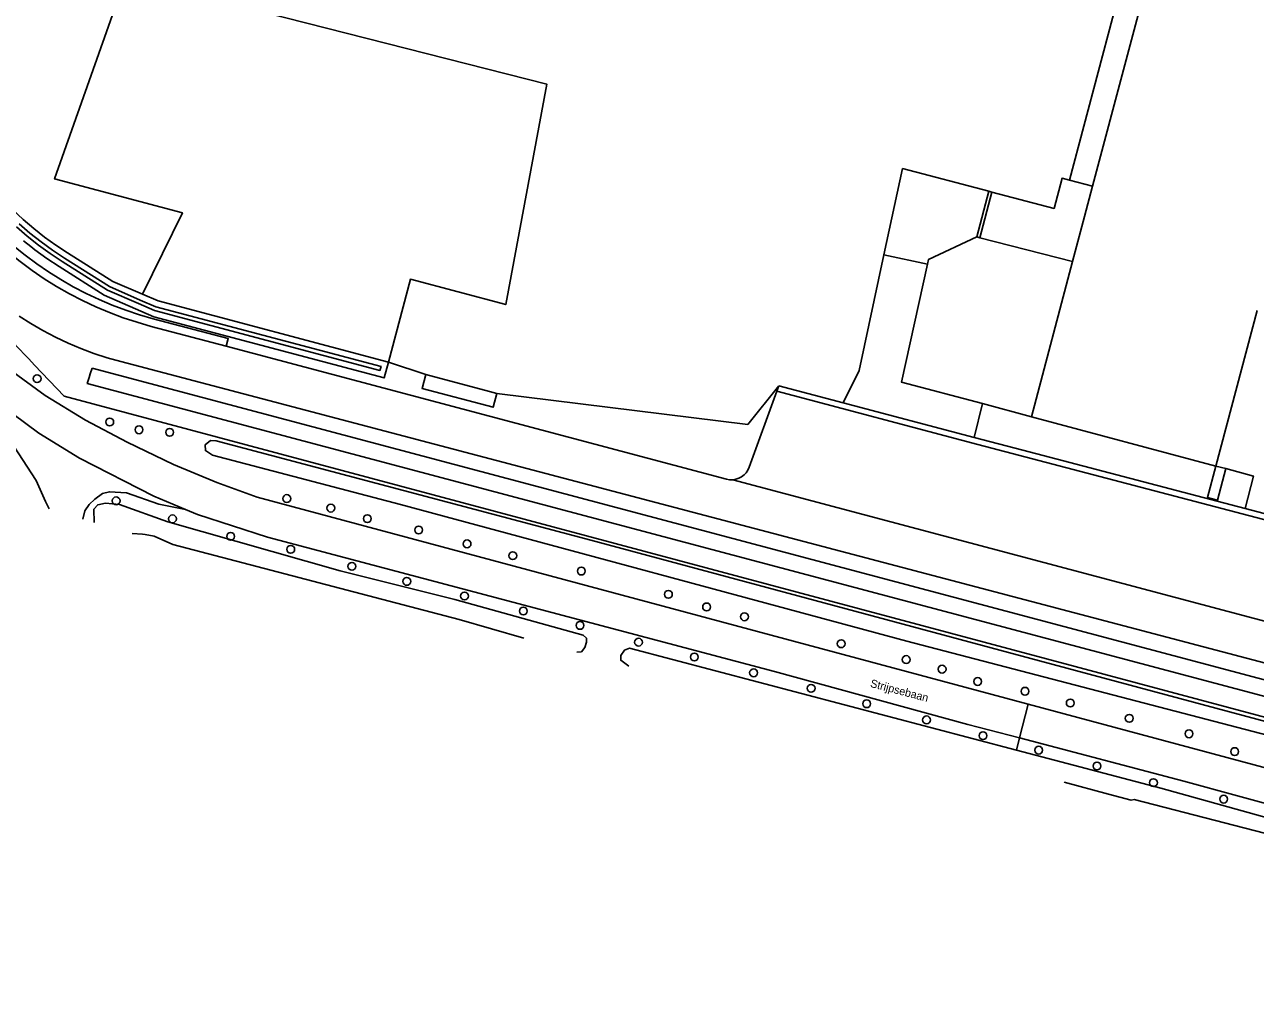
# Model space of a CAD drawing. Extents: x 152881 to 155736, y 382924 to 386919.
# Drawn here: x 154029.1 to 154182.8, y 383105 to 383226.3 of the extents above; entities that cross this region are included whole.
import ezdxf

# ---------------------------------------------------------------- set-up
doc = ezdxf.new("R2010")
doc.units = 0
for name, color, linetype in [('IMGEO_Boom', 7, 'Continuous'), ('IMGEO_Groenvoorziening', 7, 'Continuous'), ('IMGEO_Hek', 7, 'Continuous'), ('IMGEO_Loofbos', 7, 'Continuous'), ('IMGEO_Openbare_ruimte_label', 7, 'Continuous'), ('IMGEO_Pand', 7, 'Continuous'), ('IMGEO_Rijbaan_lokaal_gesloten', 7, 'Continuous'), ('IMGEO_Rijbaan_lokaal_halfverhard', 7, 'Continuous'), ('IMGEO_Rijbaan_lokaal_open', 7, 'Continuous'), ('IMGEO_Voetpad_gesloten', 7, 'Continuous'), ('IMGEO_Voetpad_op_trap', 7, 'Continuous'), ('IMGEO_Voetpad_open', 7, 'Continuous'), ('IMGEO_Waterloop', 7, 'Continuous')]:
    doc.layers.add(name, color=color, linetype=linetype)

msp = doc.modelspace()

# ---------------------------------------------------------------- linework, layer by layer
at = {"layer": 'IMGEO_Boom'}
for centre in [(154030.64, 383182.09), (154039.71, 383176.67), (154043.37, 383175.7), (154047.19, 383175.38), (154040.51, 383166.82), (154061.83, 383167.1), (154067.33, 383165.91), (154047.55, 383164.57), (154071.89, 383164.59), (154054.82, 383162.38), (154078.3, 383163.18), (154062.32, 383160.76), (154084.35, 383161.44), (154090.06, 383159.96), (154069.96, 383158.63), (154098.63, 383158.04), (154076.82, 383156.75), (154084.03, 383154.92), (154109.5, 383155.14), (154091.38, 383153.05), (154114.27, 383153.56), (154098.46, 383151.25), (154119, 383152.33), (154105.77, 383149.15), (154131.09, 383148.96), (154112.74, 383147.3), (154139.21, 383146.98), (154120.14, 383145.33), (154143.69, 383145.78), (154148.13, 383144.24), (154127.33, 383143.39), (154154.05, 383143.02), (154134.27, 383141.46), (154159.7, 383141.55), (154141.75, 383139.44), (154167.07, 383139.64), (154148.8, 383137.47), (154174.54, 383137.71), (154155.76, 383135.66), (154180.24, 383135.48), (154163.04, 383133.68), (154170.09, 383131.59), (154178.87, 383129.54)]:
    msp.add_circle(centre, 0.489, dxfattribs=at)
at = {"layer": 'IMGEO_Groenvoorziening'}
for points in [[(154296.01, 383110.08), (154286.6, 383112.34), (154034.03, 383179.91), (154030.33, 383183.78), (154029.6, 383184.55), (154029.12, 383185.06), (154028.39, 383185.82), (153891.83, 383329), (153882.74, 383329.15), (153882.71, 383329.32)], [(154054.27, 383186.13), (154054.52, 383187.09), (154045.15, 383189.58), (154043.42, 383190.08), (154041.71, 383190.65), (154040.03, 383191.28), (154038.38, 383191.98), (154036.75, 383192.74), (154035.16, 383193.57), (154033.6, 383194.46), (154032.07, 383195.42), (154030.59, 383196.43), (154029.15, 383197.5), (154027.75, 383198.63), (154026.4, 383199.82), (154025.18, 383200.97), (154024.49, 383200.24)], [(154028.94, 383199.31), (154029.85, 383198.59), (154030.37, 383198.18), (154031.86, 383197.11), (154033.38, 383196.1), (154039.02, 383192.53), (154045.21, 383189.83), (154073.99, 383182.18), (154074.52, 383184.16)], [(154074.52, 383184.16), (154045.74, 383191.81), (154043.82, 383192.63)], [(154153.38, 383137.18), (154152.98, 383135.66)]]:
    msp.add_lwpolyline(points, dxfattribs=at)
at = {"layer": 'IMGEO_Hek'}
for points in [[(154028.39, 383185.82), (154029.12, 383185.06)], [(154029.12, 383185.06), (154029.6, 383184.55)], [(154029.6, 383184.55), (154030.33, 383183.78)], [(154294.11, 383119.44), (154295.32, 383113.47), (154296.01, 383110.08), (154286.6, 383112.34), (154034.03, 383179.91), (154030.33, 383183.78)]]:
    msp.add_lwpolyline(points, dxfattribs=at)
at = {"layer": 'IMGEO_Loofbos'}
for points in [[(154165.79, 383480.92), (154156.98, 383466.93), (154155.57, 383464.69), (154156.76, 383463.94), (154167.27, 383457.31), (154127.08, 383391.98), (154141.95, 383313.16), (154155.29, 383289.09), (154162.41, 383252.83), (154169.8, 383245.38), (154168.55, 383240.68), (154159.6, 383206.89)], [(154043.82, 383192.63), (154040.1, 383194.22), (154034.45, 383197.79), (154032.99, 383198.75), (154031.58, 383199.78), (154030.21, 383200.86), (154028.88, 383201.99), (154027.6, 383203.18), (154026.37, 383204.42), (153969.96, 383263.71), (153968.87, 383264.87)], [(154074.52, 383184.16), (154077.27, 383194.5), (154089.18, 383191.34), (154094.3, 383218.9), (154041.72, 383232.3), (154032.81, 383207.04), (154048.79, 383202.79), (154043.82, 383192.63)], [(154079.18, 383182.61), (154074.52, 383184.16)], [(154123.29, 383181.18), (154119.41, 383176.34), (154088.07, 383180.25)]]:
    msp.add_lwpolyline(points, dxfattribs=at)
at = {"layer": 'IMGEO_Pand'}
for points in [[(154173.24, 383237.11), (154170.88, 383237.75), (154162.5, 383206.13)], [(154162.5, 383206.13), (154161.5, 383202.36), (154160, 383196.72)], [(154160, 383196.72), (154154.86, 383177.31)], [(154177.9, 383171.14), (154183.06, 383190.59)], [(154154.86, 383177.31), (154177.9, 383171.14)]]:
    msp.add_lwpolyline(points, dxfattribs=at)
at = {"layer": 'IMGEO_Rijbaan_lokaal_gesloten'}
for points in [[(154054.27, 383186.13), (154044.89, 383188.62), (154043.12, 383189.13), (154041.38, 383189.7), (154039.66, 383190.35), (154037.97, 383191.06), (154036.31, 383191.85), (154034.68, 383192.69), (154033.08, 383193.6), (154031.53, 383194.58), (154030.01, 383195.62), (154028.54, 383196.71), (154027.11, 383197.87), (154025.73, 383199.08), (154024.49, 383200.24)], [(154028.39, 383189.91), (154029.86, 383188.98), (154031.37, 383188.1), (154032.92, 383187.29), (154034.5, 383186.54), (154036.11, 383185.86), (154037.74, 383185.24), (154039.4, 383184.69), (154041.08, 383184.21), (154285.51, 383119.78), (154286.82, 383119.55), (154288.58, 383119.39), (154289.45, 383119.52), (154294.6, 383120.39), (154294.84, 383119.58)], [(154117.53, 383169.45), (154117.14, 383169.46), (154116.76, 383169.53), (154054.27, 383186.13)], [(154123.05, 383180.52), (154119.6, 383171.01), (154119.44, 383170.66), (154119.22, 383170.33), (154118.95, 383170.05), (154118.64, 383169.82), (154118.29, 383169.63), (154117.92, 383169.51), (154117.53, 383169.45)], [(154243.08, 383148.93), (154148.16, 383173.85), (154123.05, 383180.52)], [(154241.31, 383136.53), (154117.53, 383169.45)]]:
    msp.add_lwpolyline(points, dxfattribs=at)
at = {"layer": 'IMGEO_Rijbaan_lokaal_halfverhard'}
for points in [[(154032.13, 383165.8), (154031.68, 383166.72), (154030.54, 383169.34), (154025.99, 383176.29), (154023.57, 383179.52), (154015.93, 383186.56), (154015.99, 383187.44)], [(154049.17, 383165.75), (154045.2, 383167.4), (154035.94, 383172.13), (154030.85, 383175.27), (154024.47, 383179.99), (154015.99, 383187.44)], [(154027.14, 383183.27), (154031.63, 383179.99), (154036.69, 383176.91), (154041.89, 383174.16), (154047.67, 383171.36), (154053.09, 383169.1), (154058.11, 383167.26), (154154.46, 383141.41)], [(154036.35, 383164.54), (154036.61, 383165.57), (154037.13, 383166.34), (154037.85, 383167.04), (154038.82, 383167.72), (154039.68, 383167.95), (154041.81, 383167.83), (154045.84, 383166.42), (154049.17, 383165.75)], [(154153.38, 383137.18), (154146.89, 383138.88), (154122.76, 383145.5), (154059.4, 383162.27), (154050.69, 383165.13), (154049.17, 383165.75)], [(154154.46, 383141.41), (154153.38, 383137.18)], [(154154.46, 383141.41), (154226.11, 383122.18), (154266.39, 383111.73), (154274.12, 383109.53)], [(154272.97, 383105.01), (154250.05, 383111.69), (154234.23, 383115.28), (154173.87, 383131.78), (154153.38, 383137.18)]]:
    msp.add_lwpolyline(points, dxfattribs=at)
at = {"layer": 'IMGEO_Rijbaan_lokaal_open'}
for points in [[(154149.51, 383205.51), (154148.01, 383199.8)], [(154149.9, 383205.41), (154149.51, 383205.51)], [(154148.4, 383199.7), (154149.9, 383205.41)], [(154148.01, 383199.8), (154148.4, 383199.7)], [(154123.29, 383181.18), (154123.05, 383180.52)], [(154131.35, 383179.05), (154123.29, 383181.18)], [(154131.35, 383179.05), (154147.7, 383174.75)], [(154147.7, 383174.75), (154153.76, 383173.16), (154178.04, 383166.77)], [(154178.04, 383166.77), (154181.54, 383165.85)], [(154181.54, 383165.85), (154207.14, 383159.11)]]:
    msp.add_lwpolyline(points, dxfattribs=at)
at = {"layer": 'IMGEO_Voetpad_gesloten'}
for points in [[(154149.51, 383205.51), (154138.75, 383208.34), (154136.43, 383197.55)], [(154159.6, 383206.89), (154158.68, 383207.14), (154157.69, 383203.36), (154149.9, 383205.41)], [(154162.5, 383206.13), (154159.6, 383206.89)], [(154141.86, 383196.39), (154141.99, 383196.97), (154148.01, 383199.8)], [(154160, 383196.72), (154148.4, 383199.7)], [(154141.86, 383196.39), (154136.43, 383197.55)], [(154147.7, 383174.75), (154148.72, 383179)], [(154148.72, 383179), (154154.86, 383177.31)], [(154177.9, 383171.14), (154176.86, 383167.25), (154178.08, 383166.91)], [(154178.08, 383166.91), (154178.04, 383166.77)]]:
    msp.add_lwpolyline(points, dxfattribs=at)
at = {"layer": 'IMGEO_Voetpad_op_trap'}
msp.add_lwpolyline([(154179.13, 383170.84), (154177.9, 383171.14)], dxfattribs=at)
at = {"layer": 'IMGEO_Voetpad_open'}
for points in [[(154136.43, 383197.55), (154133.32, 383183.1), (154131.35, 383179.05)], [(154148.72, 383179), (154138.61, 383181.66), (154141.86, 383196.39)], [(154178.08, 383166.91), (154179.13, 383170.84)], [(154179.13, 383170.84), (154182.6, 383169.88), (154181.54, 383165.85)]]:
    msp.add_lwpolyline(points, dxfattribs=at)
at = {"layer": 'IMGEO_Waterloop'}
for points in [[(154028.38, 383201.43), (154029.73, 383200.28), (154031.13, 383199.18), (154032.57, 383198.14), (154034.04, 383197.16), (154039.68, 383193.59), (154043.52, 383191.91), (154045.48, 383191.07), (154073.6, 383183.61), (154073.47, 383183.12), (154045.32, 383190.6), (154043.32, 383191.46), (154039.44, 383193.15), (154033.77, 383196.74), (154032.28, 383197.73), (154030.83, 383198.78), (154029.41, 383199.89), (154028.05, 383201.06)], [(154037.5, 383183.41), (154037.28, 383182.69), (154037.13, 383182.22), (154036.91, 383181.5), (154279.63, 383116.96), (154285.99, 383114.17), (154286.79, 383116), (154280.29, 383118.85), (154037.5, 383183.41)], [(154079.18, 383182.61), (154078.72, 383180.87), (154087.61, 383178.51), (154088.07, 383180.25)], [(154088.07, 383180.25), (154087.16, 383180.49), (154079.18, 383182.61)], [(154155.86, 383146.84), (154205.05, 383133.61), (154253.56, 383120.41), (154293.05, 383110), (154292.87, 383108.88), (154253.14, 383118.76), (154206.65, 383131.7), (154155.4, 383145.06), (154139.27, 383149.26), (154076.04, 383166.38), (154052.55, 383172.51), (154051.66, 383173.09), (154051.64, 383173.82), (154052.29, 383174.34), (154052.99, 383174.33), (154099.83, 383161.9), (154155.86, 383146.84)], [(154098.08, 383147.9), (154098.63, 383147.93), (154099.05, 383148.48), (154099.28, 383149.14), (154099.25, 383149.67), (154098.86, 383150.01), (154082.83, 383154.48), (154068.49, 383158.08), (154046.97, 383164.18), (154040.91, 383166.35), (154039.17, 383166.52), (154038.22, 383166.32), (154037.74, 383165.79), (154037.76, 383164.12)], [(154047.61, 383161.38), (154045.24, 383162.4), (154044.12, 383162.61), (154043.8, 383162.67), (154042.52, 383162.74)], [(154091.44, 383149.67), (154083.37, 383151.97), (154047.61, 383161.38)], [(154152.98, 383135.66), (154104.63, 383148.39), (154104, 383148.17), (154103.56, 383147.49), (154103.55, 383146.89), (154104.57, 383146.17)], [(154237.53, 383111.19), (154238.18, 383111.39), (154238.64, 383112.24), (154238.32, 383112.88), (154215.4, 383118.73), (154193.88, 383124.52), (154171.02, 383130.91), (154152.98, 383135.66)], [(154237.53, 383111.19), (154212.83, 383117.82), (154167.69, 383129.5), (154167.32, 383129.42), (154164.49, 383130.18), (154158.96, 383131.64)]]:
    msp.add_lwpolyline(points, dxfattribs=at)

# ---------------------------------------------------------------- texts
at = {"layer": 'IMGEO_Openbare_ruimte_label'}
msp.add_text('Strijpsebaan', height=1, rotation=345.2273, dxfattribs=at).set_placement((154134.65, 383143.58))

doc.saveas('drawing.dxf')
